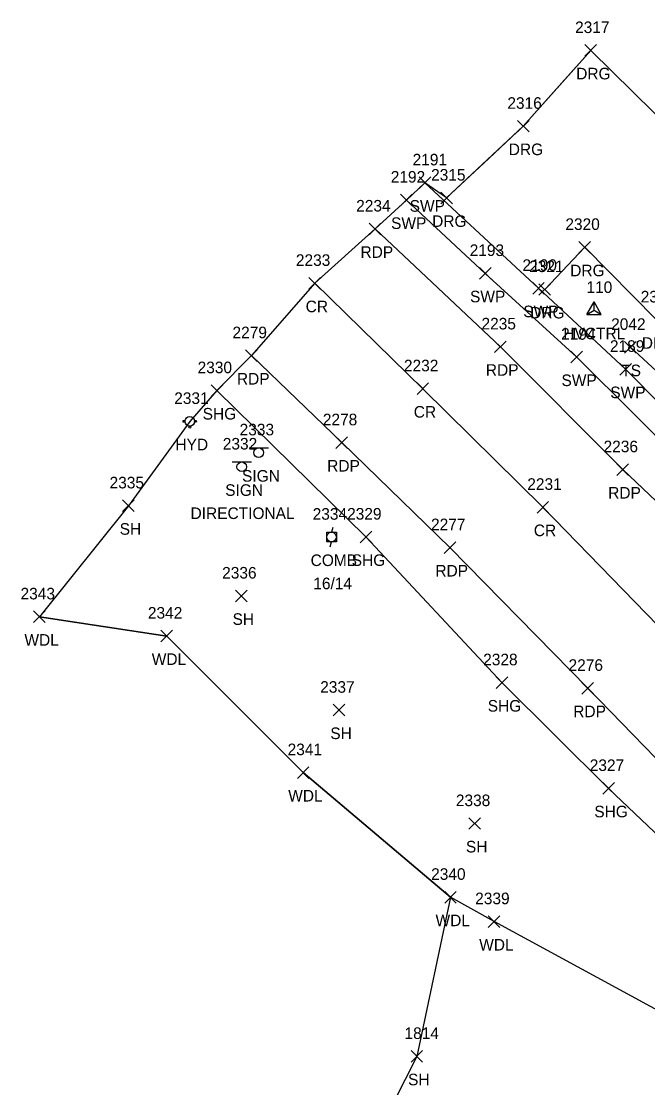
# Model space of a CAD drawing. Extents: x 1616726 to 1619875, y 273782 to 276557.
# Drawn here: x 1616726.5 to 1616834.7, y 276373.3 to 276557.4 of the extents above; entities that cross this region are included whole.
import ezdxf

# ---------------------------------------------------------------- set-up
doc = ezdxf.new("R2010")
doc.units = 0
for name, color, linetype in [('C_A', 7, 'Continuous'), ('C_I', 7, 'Continuous'), ('CPSM', 7, 'Continuous'), ('L_A', 7, 'Continuous'), ('L_I', 7, 'Continuous'), ('L_TIC', 7, 'Continuous'), ('LAWA', 7, 'Continuous'), ('LELB', 7, 'Continuous'), ('LSOGP', 7, 'Continuous'), ('P_A', 7, 'Continuous'), ('P_I', 7, 'Continuous'), ('P_TIC', 7, 'Continuous'), ('PET', 7, 'Continuous'), ('PRC', 7, 'Continuous'), ('PSU', 7, 'Continuous'), ('R_A', 7, 'Continuous'), ('R_I', 7, 'Continuous'), ('R_TIC', 7, 'Continuous'), ('RDG', 7, 'Continuous'), ('RSW', 7, 'Continuous'), ('S_A', 7, 'Continuous'), ('S_C', 7, 'Continuous'), ('S_I', 7, 'Continuous'), ('SSGN', 7, 'Continuous'), ('U_A', 7, 'Continuous'), ('U_C', 7, 'Continuous'), ('U_I', 7, 'Continuous'), ('UP', 7, 'Continuous'), ('UWFH', 7, 'Continuous')]:
    doc.layers.add(name, color=color, linetype=linetype)

msp = doc.modelspace()

# ---------------------------------------------------------------- linework, layer by layer
at = {"layer": 'CPSM'}
for p, q in [((1616824.17, 276506.8), (1616825.42, 276508.96)), ((1616824.17, 276506.8), (1616825.42, 276507.52)), ((1616826.67, 276506.8), (1616825.42, 276508.96)), ((1616825.42, 276507.52), (1616825.42, 276508.96)), ((1616825.42, 276507.52), (1616825.42, 276507.52)), ((1616825.42, 276507.52), (1616826.67, 276506.8)), ((1616824.17, 276506.8), (1616826.67, 276506.8))]:
    msp.add_line(p, q, dxfattribs=at)
at = {"layer": 'L_TIC'}
for points in [[(1616830.71, 276500.14), (1616832.71, 276502.14)], [(1616832.71, 276500.14), (1616830.71, 276502.14)], [(1616743.98, 276472.77), (1616745.98, 276474.77)], [(1616745.98, 276472.77), (1616743.98, 276474.77)], [(1616763.48, 276457.2), (1616765.48, 276459.2)], [(1616765.48, 276457.2), (1616763.48, 276459.2)], [(1616728.6, 276453.6), (1616730.6, 276455.6)], [(1616730.6, 276453.6), (1616728.6, 276455.6)], [(1616750.6, 276450.28), (1616752.6, 276452.28)], [(1616752.6, 276450.28), (1616750.6, 276452.28)], [(1616780.37, 276437.48), (1616782.37, 276439.48)], [(1616782.37, 276437.48), (1616780.37, 276439.48)], [(1616774.17, 276426.7), (1616776.17, 276428.7)], [(1616776.17, 276426.7), (1616774.17, 276428.7)], [(1616803.81, 276417.9), (1616805.81, 276419.9)], [(1616805.81, 276417.9), (1616803.81, 276419.9)], [(1616799.62, 276405.17), (1616801.62, 276407.17)], [(1616801.62, 276405.17), (1616799.62, 276407.17)], [(1616807.16, 276400.96), (1616809.16, 276402.96)], [(1616809.16, 276400.96), (1616807.16, 276402.96)], [(1616793.81, 276377.69), (1616795.81, 276379.69)], [(1616795.81, 276377.69), (1616793.81, 276379.69)]]:
    msp.add_lwpolyline(points, dxfattribs=at)
at = {"layer": 'LAWA'}
msp.add_lwpolyline([(1616926.41, 276312.56), (1616914.58, 276324.87), (1616905.26, 276338.6), (1616897.95, 276344.34), (1616892.13, 276347.37), (1616881.86, 276360.64), (1616871.25, 276371.07), (1616853.28, 276386.36), (1616841.14, 276384.08), (1616808.16, 276401.96), (1616800.62, 276406.17), (1616775.17, 276427.7), (1616751.6, 276451.28), (1616729.6, 276454.6)], dxfattribs=at)
at = {"layer": 'LELB'}
msp.add_lwpolyline([(1616864.86, 276470.77), (1616855.17, 276479.74), (1616847.76, 276486.31), (1616839.13, 276494.29), (1616831.71, 276501.14)], dxfattribs=at)
at = {"layer": 'LSOGP'}
msp.add_lwpolyline([(1616853.98, 276523.8), (1616824.85, 276552.4), (1616819.85, 276546.79), (1616813.2, 276539.32), (1616807.26, 276533.75), (1616799.96, 276526.92), (1616796.2, 276529.55), (1616793, 276526.57), (1616787.59, 276521.58), (1616777.17, 276512.19), (1616766.23, 276499.7), (1616760.28, 276493.66), (1616755.58, 276488.35), (1616744.98, 276473.77), (1616729.6, 276454.6), (1616751.6, 276451.28), (1616775.17, 276427.7), (1616800.62, 276406.17), (1616794.81, 276378.69), (1616788.7, 276366.66)], dxfattribs=at)
at = {"layer": 'P_TIC'}
for points in [[(1616786.59, 276520.58), (1616788.59, 276522.58)], [(1616788.59, 276520.58), (1616786.59, 276522.58)], [(1616776.17, 276511.19), (1616778.17, 276513.19)], [(1616778.17, 276511.19), (1616776.17, 276513.19)], [(1616808.24, 276500.22), (1616810.24, 276502.22)], [(1616810.24, 276500.22), (1616808.24, 276502.22)], [(1616765.23, 276498.7), (1616767.23, 276500.7)], [(1616767.23, 276498.7), (1616765.23, 276500.7)], [(1616759.28, 276492.66), (1616761.28, 276494.66)], [(1616761.28, 276492.66), (1616759.28, 276494.66)], [(1616794.84, 276492.99), (1616796.84, 276494.99)], [(1616796.84, 276492.99), (1616794.84, 276494.99)], [(1616780.83, 276483.67), (1616782.83, 276485.67)], [(1616782.83, 276483.67), (1616780.83, 276485.67)], [(1616829.38, 276479.01), (1616831.38, 276481.01)], [(1616831.38, 276479.01), (1616829.38, 276481.01)], [(1616815.58, 276472.52), (1616817.58, 276474.52)], [(1616817.58, 276472.52), (1616815.58, 276474.52)], [(1616785.02, 276467.38), (1616787.02, 276469.38)], [(1616787.02, 276467.38), (1616785.02, 276469.38)], [(1616799.52, 276465.55), (1616801.52, 276467.55)], [(1616801.52, 276465.55), (1616799.52, 276467.55)], [(1616808.53, 276442.22), (1616810.53, 276444.22)], [(1616810.53, 276442.22), (1616808.53, 276444.22)], [(1616823.34, 276441.26), (1616825.34, 276443.26)], [(1616825.34, 276441.26), (1616823.34, 276443.26)], [(1616826.94, 276423.97), (1616828.94, 276425.97)], [(1616828.94, 276423.97), (1616826.94, 276425.97)]]:
    msp.add_lwpolyline(points, dxfattribs=at)
at = {"layer": 'PET'}
for points in [[(1616787.59, 276521.58), (1616809.24, 276501.22), (1616830.38, 276480.01), (1616850.02, 276461.38), (1616866.44, 276444.54), (1616873.55, 276441.17), (1616892.87, 276425.54), (1616905.78, 276413.31), (1616922.09, 276405.95), (1616942.2, 276398.95), (1616962.48, 276398.53), (1616981.09, 276402.37)], [(1616900.38, 276364.1), (1616887.78, 276376.03), (1616868.94, 276396.45), (1616849.67, 276416.18), (1616824.34, 276442.26), (1616800.52, 276466.55), (1616781.83, 276484.67), (1616766.23, 276499.7)]]:
    msp.add_lwpolyline(points, dxfattribs=at)
at = {"layer": 'PRC'}
msp.add_lwpolyline([(1616953.09, 276321.77), (1616937.3, 276341.18), (1616917.35, 276364.38), (1616896.09, 276388.68), (1616870.6, 276416.95), (1616844.42, 276444.9), (1616816.58, 276473.52), (1616795.84, 276493.99), (1616777.17, 276512.19)], dxfattribs=at)
at = {"layer": 'PSU'}
msp.add_lwpolyline([(1616885.84, 276375.81), (1616869.35, 276386.82), (1616846.05, 276407.76), (1616827.94, 276424.97), (1616809.53, 276443.22), (1616786.02, 276468.38), (1616760.28, 276493.66)], dxfattribs=at)
at = {"layer": 'R_TIC'}
for points in [[(1616823.85, 276551.4), (1616825.85, 276553.4)], [(1616825.85, 276551.4), (1616823.85, 276553.4)], [(1616812.2, 276538.32), (1616814.2, 276540.32)], [(1616814.2, 276538.32), (1616812.2, 276540.32)], [(1616795.2, 276528.55), (1616797.2, 276530.55)], [(1616797.2, 276528.55), (1616795.2, 276530.55)], [(1616798.96, 276525.92), (1616800.96, 276527.92)], [(1616800.96, 276525.92), (1616798.96, 276527.92)], [(1616792, 276525.57), (1616794, 276527.57)], [(1616794, 276525.57), (1616792, 276527.57)], [(1616822.82, 276517.4), (1616824.82, 276519.4)], [(1616824.82, 276517.4), (1616822.82, 276519.4)], [(1616805.64, 276512.9), (1616807.64, 276514.9)], [(1616807.64, 276512.9), (1616805.64, 276514.9)], [(1616814.83, 276510.33), (1616816.83, 276512.33)], [(1616816.83, 276510.33), (1616814.83, 276512.33)], [(1616815.9, 276510.12), (1616817.9, 276512.12)], [(1616817.9, 276510.12), (1616815.9, 276512.12)], [(1616821.44, 276498.44), (1616823.44, 276500.44)], [(1616823.44, 276498.44), (1616821.44, 276500.44)], [(1616829.87, 276496.35), (1616831.87, 276498.35)], [(1616831.87, 276496.35), (1616829.87, 276498.35)]]:
    msp.add_lwpolyline(points, dxfattribs=at)
at = {"layer": 'RDG'}
for points in [[(1616799.96, 276526.92), (1616813.2, 276539.32), (1616824.85, 276552.4)], [(1616853.98, 276523.8), (1616836.2, 276505.88), (1616823.82, 276518.4), (1616816.9, 276511.12)]]:
    msp.add_lwpolyline(points, dxfattribs=at)
at = {"layer": 'RSW'}
for points in [[(1616979.18, 276402.58), (1616970.93, 276402.28), (1616960.75, 276403.53), (1616947.75, 276406.07), (1616931.67, 276410.77), (1616917.99, 276418.15), (1616909.17, 276424.63), (1616898.61, 276433.98), (1616883.06, 276447.99), (1616873.99, 276456.3), (1616860.19, 276469.07), (1616843.86, 276484.23), (1616830.87, 276497.35), (1616815.83, 276511.33), (1616796.2, 276529.55)], [(1616793, 276526.57), (1616806.64, 276513.9), (1616822.44, 276499.44), (1616842.9, 276479.1), (1616862.42, 276460.7), (1616874.12, 276449.86), (1616881.51, 276443.96), (1616898.31, 276429.07), (1616904.59, 276422.09), (1616914.85, 276414.69), (1616926.19, 276408.67), (1616938.69, 276404.25), (1616951.3, 276401.58), (1616951.76, 276400.21)]]:
    msp.add_lwpolyline(points, dxfattribs=at)
at = {"layer": 'SSGN'}
for p, q in [((1616765.83, 276483.78), (1616769.16, 276483.78)), ((1616767.47, 276482.95), (1616767.47, 276482.95)), ((1616762.92, 276481.33), (1616766.25, 276481.33)), ((1616764.56, 276480.5), (1616764.56, 276480.5))]:
    msp.add_line(p, q, dxfattribs=at)
for centre in [(1616767.47, 276482.95), (1616764.56, 276480.5)]:
    msp.add_circle(centre, 0.833, dxfattribs=at)
at = {"layer": 'UP'}
for p, q in [((1616779.24, 276467.52), (1616779.24, 276469.19)), ((1616779.24, 276469.19), (1616780.91, 276469.19)), ((1616780.32, 276470.02), (1616780.07, 276469.19)), ((1616780.91, 276469.19), (1616780.91, 276467.52)), ((1616780.91, 276467.52), (1616779.24, 276467.52)), ((1616779.82, 276466.69), (1616780.07, 276467.52)), ((1616780.07, 276468.36), (1616780.07, 276468.36))]:
    msp.add_line(p, q, dxfattribs=at)
msp.add_circle((1616780.07, 276468.36), 0.833, dxfattribs=at)
at = {"layer": 'UWFH'}
msp.add_line((1616755.58, 276488.35), (1616755.58, 276488.35), dxfattribs=at)
for centre, radius in [((1616755.58, 276488.35), 0.833), ((1616754.58, 276488.35), 0.167), ((1616755.58, 276487.35), 0.167), ((1616756.58, 276488.35), 0.167)]:
    msp.add_circle(centre, radius, dxfattribs=at)

# ---------------------------------------------------------------- texts
at = {"layer": 'C_A'}
msp.add_text('HVCTRL', height=2, dxfattribs=at).set_placement((1616820.12, 276502.52))
at = {"layer": 'C_I'}
msp.add_text('110', height=2, dxfattribs=at).set_placement((1616824.11, 276510.52))
at = {"layer": 'L_A'}
for s, p in [('TS', (1616830.12, 276496.14)), ('SH', (1616743.47, 276468.77)), ('SH', (1616762.97, 276453.2)), ('WDL', (1616727.01, 276449.6)), ('WDL', (1616749.01, 276446.28)), ('SH', (1616779.86, 276433.48)), ('WDL', (1616772.59, 276422.7)), ('SH', (1616803.29, 276413.9)), ('WDL', (1616798.04, 276401.17)), ('WDL', (1616805.58, 276396.96)), ('SH', (1616793.29, 276373.69))]:
    msp.add_text(s, height=2, dxfattribs=at).set_placement(p)
at = {"layer": 'L_I'}
for s, p in [('2042', (1616828.38, 276504.14)), ('2335', (1616741.72, 276476.77)), ('2336', (1616761.17, 276461.2)), ('2343', (1616726.34, 276457.6)), ('2342', (1616748.34, 276454.28)), ('2337', (1616778.11, 276441.48)), ('2341', (1616772.48, 276430.7)), ('2338', (1616801.55, 276421.9)), ('2340', (1616797.28, 276409.17)), ('2339', (1616804.89, 276404.96)), ('1814', (1616792.68, 276381.69))]:
    msp.add_text(s, height=2, dxfattribs=at).set_placement(p)
at = {"layer": 'P_A'}
for s, p in [('RDP', (1616785.07, 276516.58)), ('CR', (1616775.6, 276507.19)), ('RDP', (1616806.73, 276496.22)), ('RDP', (1616763.72, 276494.7)), ('CR', (1616794.28, 276488.99)), ('SHG', (1616757.81, 276488.66)), ('RDP', (1616779.32, 276479.67)), ('RDP', (1616827.87, 276475.01)), ('CR', (1616815.02, 276468.52)), ('SHG', (1616783.56, 276463.38)), ('RDP', (1616798.01, 276461.55)), ('SHG', (1616807.06, 276438.22)), ('RDP', (1616821.83, 276437.26)), ('SHG', (1616825.47, 276419.97))]:
    msp.add_text(s, height=2, dxfattribs=at).set_placement(p)
at = {"layer": 'P_I'}
for s, p in [('2234', (1616784.33, 276524.58)), ('2233', (1616773.91, 276515.19)), ('2235', (1616805.98, 276504.22)), ('2279', (1616762.96, 276502.7)), ('2330', (1616756.93, 276496.66)), ('2232', (1616792.58, 276496.99)), ('2278', (1616778.57, 276487.67)), ('2236', (1616827.07, 276483.01)), ('2231', (1616813.89, 276476.52)), ('2329', (1616782.76, 276471.38)), ('2277', (1616797.26, 276469.55)), ('2328', (1616806.27, 276446.22)), ('2276', (1616821.02, 276445.26)), ('2327', (1616824.68, 276427.97))]:
    msp.add_text(s, height=2, dxfattribs=at).set_placement(p)
at = {"layer": 'R_A'}
for s, p in [('DRG', (1616822.34, 276547.4)), ('DRG', (1616810.69, 276534.32)), ('SWP', (1616793.57, 276524.55)), ('DRG', (1616797.45, 276521.92)), ('SWP', (1616790.36, 276521.57)), ('DRG', (1616821.31, 276513.4)), ('SWP', (1616804, 276508.9)), ('SWP', (1616813.2, 276506.33)), ('DRG', (1616814.39, 276506.12)), ('DRG', (1616833.68, 276500.88)), ('SWP', (1616819.8, 276494.44)), ('SWP', (1616828.23, 276492.35))]:
    msp.add_text(s, height=2, dxfattribs=at).set_placement(p)
at = {"layer": 'R_I'}
for s, p in [('2317', (1616822.15, 276555.4)), ('2316', (1616810.45, 276542.32)), ('2191', (1616794.08, 276532.55)), ('2192', (1616790.3, 276529.57)), ('2315', (1616797.27, 276529.92)), ('2320', (1616820.47, 276521.4)), ('2193', (1616803.94, 276516.9)), ('2190', (1616813.06, 276514.33)), ('2321', (1616814.21, 276514.12)), ('2319', (1616833.49, 276508.88)), ('2194', (1616819.74, 276502.44)), ('2189', (1616828.17, 276500.35))]:
    msp.add_text(s, height=2, dxfattribs=at).set_placement(p)
at = {"layer": 'S_A'}
for p in [(1616764.61, 276477.93), (1616761.7, 276475.48)]:
    msp.add_text('SIGN', height=2, dxfattribs=at).set_placement(p)
at = {"layer": 'S_C'}
msp.add_text('DIRECTIONAL', height=2, dxfattribs=at).set_placement((1616755.71, 276471.48))
at = {"layer": 'S_I'}
for s, p in [('2333', (1616764.19, 276485.93)), ('2332', (1616761.28, 276483.48))]:
    msp.add_text(s, height=2, dxfattribs=at).set_placement(p)
at = {"layer": 'U_A'}
for s, p in [('HYD', (1616753.1, 276483.35)), ('COMB', (1616776.46, 276463.36))]:
    msp.add_text(s, height=2, dxfattribs=at).set_placement(p)
at = {"layer": 'U_C'}
msp.add_text('16/14', height=2, dxfattribs=at).set_placement((1616776.92, 276459.36))
at = {"layer": 'U_I'}
for s, p in [('2331', (1616752.89, 276491.35)), ('2334', (1616776.81, 276471.36))]:
    msp.add_text(s, height=2, dxfattribs=at).set_placement(p)

doc.saveas('drawing.dxf')
